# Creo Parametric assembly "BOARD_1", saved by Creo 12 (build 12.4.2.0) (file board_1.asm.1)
Units: Custom; MM, KILOGRAM, SECS

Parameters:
  PTC_WM_ITERATION = "0"
  PTC_WM_VERSION = "-.0"
  PTC_WM_LIFECYCLE_STATE = "In Work"
  PTC_WM_LIFECYCLE = "MO_CADDocument"
  PTC_WM_CREATED_BY = "Maximilian Roepper (Z0017RMS: MO)"
  PTC_WM_CREATED_ON = "18-Sep-26 11:36:42 AM"
  PTC_WM_MODIFIED_BY = "Maximilian Roepper (Z0017RMS: MO)"
  PTC_WM_MODIFIED_ON = "18-Sep-26 11:36:46 AM"
  PDMLINKNUMBER = "PDM000071454876"
  PTC_WM_NUMBER = "PDM000071454876"

Other parameters: WEIGHT, WEIGHT_FACTOR, WEIGHT_ADD, MC_ERRORS, SUPPLIER

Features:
  1. coordinate system
  2. imported feature
  3. component "PLATE_AND_HOLES_1"
  4. component "SILK_UPPER_1"
  5. component "CUPPER_UPPER_1"
  6. component "CUPPER_BOTTOM_1"
  7. component "MASK_BOTTOM_1"
  8. component "SILK_BOTTOM_1"
  9. component "COMPONENTS_1"
  10. component "MASK_UPPER_1"

Other named items: DRW_VIEW_ORG, ROUGH-GROB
